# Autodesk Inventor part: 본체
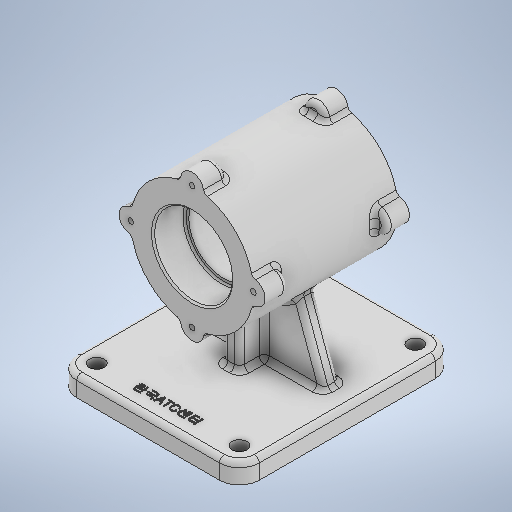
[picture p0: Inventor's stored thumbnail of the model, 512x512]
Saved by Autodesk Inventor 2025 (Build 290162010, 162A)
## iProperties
Created: 2024-08
Part Number: 본체
Material: 일반
Document SubType Name: Modeling
Designer: 학생
Density: 1 g/cm^3
Appearance: 기본값
Mass: 450.142 g
Surface Area: 796.85 cm^2
Volume: 450.142 cm^3
Author: 학생
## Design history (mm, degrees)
sketch "스케치1"
  geometry: L1 (55, 70)-(-55, 70); L2 (-55, 70)-(-55, -60); L3 (-55, -60)-(55, -60); L4 (55, -60)-(55, 70); L5 (0, 0)-(0, -7.399); L6 (0, 0)-(6.141, 0)
  constraints: 12 end point, 2 horizontal, 2 parallel, 1 perpendicular, 1 vertical, 1 other
  dimensions: "d0" = 130 distance of L3.end L1.start; "d1" = 110 distance of L2.end L3.end; "d12" = 70 distance from line of L1 L5.start
extrude "돌출1" new body sketch "스케치1" distance "d2" = 12; taper "d3" = 0 deg
fillet "모깎기1" dims "d4" = 12
sketch "스케치2" dims "d5" = 74
  geometry: L1 (-43, 0)-(43, 0) reference; C1 r 7 at (0, 119); C2 r 7 at (-37, 82); C3 r 7 at (0, 45); C4 r 7 at (37, 82); 12 further points
  constraints: 4 centre point, 2 midpoint, 2 vertical alignment, 12 other
  dimensions: "d6" = 82 distance of point (0, 0) point (0, 82); "d7" = 14 diameter of C1; "d10" = 360 deg dimension on point (0, 82) C1.centre (derived)
  node "스케치 - 원형 패턴1" dims "d10" = 360 deg (derived)
extrude "돌출2" join sketch "스케치2" stored distance "d13" = 87; taper "d14" = 0 deg
extrude "돌출3" cut sketch "스케치2" stored distance "d15" = 59; taper "d16" = 0 deg
sketch "스케치3"
  geometry: L1 (-2, 20)-(2, 20); L2 (5, 17)-(5, -17); L3 (2, -20)-(-2, -20); L4 (-5, -17)-(-5, 17); L5 (-43, 0)-(43, 0) reference; L6 (0, 0)-(0, 6.072); A1 r 3 centre (2, 17) between (5, 17) and (2, 20); A2 r 3 centre (-2, 17) between (-2, 20) and (-5, 17); A3 r 3 centre (-2, -17) between (-5, -17) and (-2, -20); A4 r 3 centre (2, -17) between (2, -20) and (5, -17); 3 further points
  constraints: 10 end point, 8 point on circle, 8 tangent, 6 point on line, 4 centre point, 3 equal radius, 2 parallel, 1 horizontal, 1 perpendicular, 1 vertical, 2 other
  dimensions: "d17" = 10 distance of point (-5, 20) point (5, 20); "d18" = 40 distance of point (-5, -20) point (-5, 20); "d19" = 3 radius of A1
extrude "돌출4" join sketch "스케치3" stored distance "d20" = 59; taper "d21" = 0 deg
sketch "스케치4"
  geometry: L1 (-41, 5)-(41, 5); L2 (41, 5)-(41, -5); L3 (41, -5)-(-41, -5); L4 (-41, -5)-(-41, 5); L5 (0, 0)-(0, 9.752); L6 (-43, 0)-(43, 0) reference
  constraints: 10 end point, 2 parallel, 1 horizontal, 1 perpendicular, 1 vertical, 2 other
  dimensions: "d22" = 10 distance of L3.end L1.start; "d23" = 82 distance of L2.end L3.end
extrude "돌출5" join sketch "스케치4" distance "d24" = 60; taper "d25" = 0 deg
feature "면 기울기1" dims angle "d26" = 20 deg
feature "면 기울기2" dims angle "d27" = 20 deg
sketch "스케치5"
  geometry: L1 (89, 43.5)-(75, 43.5) reference; L2 (82, 43.5)-(82, -43.5); L3 (75, -43.5)-(89, -43.5) reference; L4 (82, 43.5)-(105.5, 43.5); L5 (105.5, 43.5)-(105.5, 24.5); L6 (105.5, 24.5)-(103, 24.5); L7 (103, 24.5)-(103, -24.5); L8 (103, -24.5)-(105.5, -24.5); L9 (105.5, -24.5)-(105.5, -43.5); L10 (105.5, -43.5)-(82, -43.5); 7 further points
  constraints: 16 end point, 4 perpendicular, 2 equal length, 2 horizontal, 2 midpoint, 1 collinear
  dimensions: "d28" = 19 distance of L4.end L5.end; "d29" = 23.5 distance of L2.start L4.end; "d30" = 21 distance between parallel lines of L2 L7
revolve "회전1" sketch "스케치5" stored, may be unused: angle "d31" = 90 deg
sketch "스케치6"
  geometry: 2 further points
  constraints: 1 vertical alignment, 1 other
  dimensions: "d32" = 58 distance of point (0, -58) point (0, 0)
feature "엠보싱1" sketch "스케치6" dims "d0" = 130, "d1" = 110, "d5" = 74, "d6" = 82, "d7" = 14, "d10" = 360 deg (derived), "d12" = 70, "d33" = 0.5, "d34" = 0
chamfer "모따기1" distance "d35" = 1; stored, may be unused: second distance "d36" = 2, angle "d37" = 45 deg
fillet "모깎기2" dims "d38" = 1
fillet "모깎기3" dims "d39" = 1
fillet "모깎기4" dims "d40" = 3
fillet "모깎기5" dims "d41" = 3
fillet "모깎기6" dims "d42" = 3
fillet "모깎기7" dims "d43" = 3
sketch "스케치7"
  geometry: L1 (-43, -70)-(43, -70) reference; L2 (-55, 48)-(-55, -58) reference; 2 further points
  dimensions: "d47" = 12 distance from line of L1 point (-43, -58); "d48" = 12 distance from line of L2 point (-43, -58)
hole "구멍1" sketch "스케치7" at (-43, -58) diameter "d49" = 9; stored, may be unused: countersink angle "d53" = 90 deg, drill point angle "d55" = 0 deg; dims "d50" = 6, "d51" = 14, "d52" = 19, "d54" = 12
node "작업 평면1"
sketch "스케치8"
  geometry: C1 r 24.5 at (0, 82) reference; A1 r 37 centre (0, 82) between (-9.104, 117.863) and (-35.862, 91.104) reference; A2 r 3 centre (-38.77, 91.842) between (-38.239, 88.889) and (-35.862, 91.104) reference; A3 r 7 centre (-37, 82) between (-38.239, 88.889) and (-38.239, 75.111) reference; A4 r 3 centre (-38.77, 72.158) between (-35.862, 72.896) and (-38.239, 75.111) reference; A5 r 37 centre (0, 82) between (-35.862, 72.896) and (-9.104, 46.138) reference; A6 r 3 centre (-9.842, 43.23) between (-6.889, 43.761) and (-9.104, 46.138) reference; A7 r 7 centre (0, 45) between (-6.889, 43.761) and (6.889, 43.761) reference; A8 r 3 centre (9.842, 43.23) between (9.104, 46.138) and (6.889, 43.761) reference; A9 r 37 centre (0, 82) between (9.104, 46.138) and (35.863, 72.896) reference; A10 r 3 centre (38.77, 72.158) between (38.239, 75.111) and (35.863, 72.896) reference; A11 r 7 centre (37, 82) between (38.239, 75.111) and (38.239, 88.889) reference; A12 r 3 centre (38.77, 91.842) between (35.863, 91.104) and (38.239, 88.889) reference; A13 r 37 centre (0, 82) between (35.863, 91.104) and (9.104, 117.863) reference; A14 r 3 centre (9.842, 120.77) between (6.889, 120.239) and (9.104, 117.863) reference; A15 r 7 centre (0, 119) between (6.889, 120.239) and (-6.889, 120.239) reference; A16 r 3 centre (-9.842, 120.77) between (-9.104, 117.863) and (-6.889, 120.239) reference; 5 further points
  constraints: 4 coincident
hole "구멍2" sketch "스케치8" at (0, 119), (37, 82), (-37, 82), (0, 45) diameter "d57" = 3.242; stored, may be unused: countersink angle "d61" = 90 deg, drill point angle "d63" = 118 deg; dims "d58" = 8, "d59" = 4, "d60" = 2, "d62" = 10
node "작업 평면2"
fillet "모깎기8" dims "d64" = 3
fillet "모깎기9" dims "d65" = 3
sketch "스케치9"
  geometry: L1 (55, -58)-(55, 48) reference; L2 (55, 0)-(55, 14); L3 (55.304, 0)-(41.304, 0); L4 (-55, 48)-(-55, -58) reference; L5 (-55, 0)-(-55, -14); L6 (-55, 0)-(-41, 0); 1 further point
  constraints: 8 end point, 4 point on line, 2 horizontal
  dimensions: "d67" = 14 distance of L3.start L3.end; "d70" = 14 distance of L5.start L6.end
node "솔리드1"
pattern_circular "원형 패턴1" dims "d45" = 360 deg
mirror "미러1"
mirror "미러2"
mirror "미러3"
node "투영된 루프1"
feature "A9D066F2-1C7D-4E18-AEED-F7BC21143FA4" dims "d49" = 9, "d50" = 6, "d51" = 14, "d52" = 19, "d53" = 90 deg, "d54" = 12, "d55" = 0
